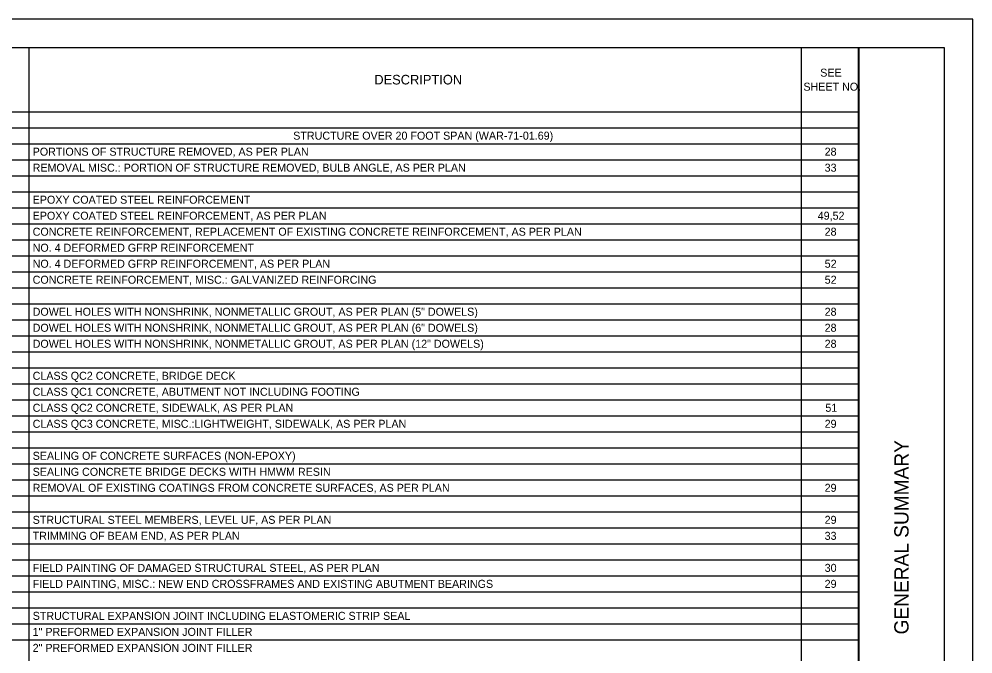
# Model space of a CAD drawing. Extents: x 0 to 34, y 0 to 22.
# Drawn here: x 17.32 to 34, y 10.89 to 22 of the extents above; entities that cross this region are included whole.
import ezdxf

# ---------------------------------------------------------------- set-up
doc = ezdxf.new("R2010")
doc.units = 0
for name, color, linetype in [('Default', 7, 'Continuous'), ('SH_Border', 7, 'Continuous'), ('SH_Cut_Line', 7, 'Continuous'), ('SH_Data', 7, 'Continuous')]:
    doc.layers.add(name, color=color, linetype=linetype)

msp = doc.modelspace()

# ---------------------------------------------------------------- linework, layer by layer
at = {"layer": 'Default'}
for p, q in [((1.5, 21.5), (32.004, 21.5)), ((17.493, 21.5), (17.493, 0.5)), ((30.999, 21.5), (30.999, 0.5)), ((32.004, 21.5), (32.004, 0.5)), ((1.5, 20.38), (32.004, 20.38)), ((1.5, 20.1), (32.004, 20.1)), ((1.5, 19.82), (32.004, 19.82)), ((1.5, 19.54), (32.004, 19.54)), ((1.5, 19.26), (32.004, 19.26)), ((1.5, 18.98), (32.004, 18.98)), ((1.5, 18.7), (32.004, 18.7)), ((1.5, 18.42), (32.004, 18.42)), ((1.5, 18.14), (32.004, 18.14)), ((1.5, 17.86), (32.004, 17.86)), ((1.5, 17.58), (32.004, 17.58)), ((1.5, 17.3), (32.004, 17.3)), ((1.5, 17.02), (32.004, 17.02)), ((1.5, 16.74), (32.004, 16.74)), ((1.5, 16.46), (32.004, 16.46)), ((1.5, 16.18), (32.004, 16.18)), ((1.5, 15.9), (32.004, 15.9)), ((1.5, 15.62), (32.004, 15.62)), ((1.5, 15.34), (32.004, 15.34)), ((1.5, 15.06), (32.004, 15.06)), ((1.5, 14.78), (32.004, 14.78)), ((1.5, 14.5), (32.004, 14.5)), ((1.5, 14.22), (32.004, 14.22)), ((1.5, 13.94), (32.004, 13.94)), ((1.5, 13.66), (32.004, 13.66)), ((1.5, 13.38), (32.004, 13.38)), ((1.5, 13.1), (32.004, 13.1)), ((1.5, 12.82), (32.004, 12.82)), ((1.5, 12.54), (32.004, 12.54)), ((1.5, 12.26), (32.004, 12.26)), ((1.5, 11.98), (32.004, 11.98)), ((1.5, 11.7), (32.004, 11.7)), ((1.5, 11.42), (32.004, 11.42)), ((1.5, 11.14), (32.004, 11.14))]:
    msp.add_line(p, q, dxfattribs=at)
at = {"layer": 'SH_Border'}
msp.add_line((32, 0.5), (32, 21.5), dxfattribs=at)
msp.add_lwpolyline([(1.5, 21.5), (33.5, 21.5), (33.5, 0.5), (1.5, 0.5)], close=True, dxfattribs=at)
at = {"layer": 'SH_Cut_Line'}
msp.add_lwpolyline([(0, 0), (34, 0), (34, 22), (0, 22)], close=True, dxfattribs=at)

# ---------------------------------------------------------------- texts
at = {"layer": 'Default'}
for s, height, p in [('DESCRIPTION', 0.168, (23.533, 20.856)), ('SEE ', 0.14, (31.33, 20.992)), ('SHEET NO.', 0.14, (31.036, 20.747)), ('STRUCTURE OVER 20 FOOT SPAN (WAR-71-01.69)', 0.14, (22.115, 19.89)), ('PORTIONS OF STRUCTURE REMOVED, AS PER PLAN', 0.14, (17.559, 19.61)), ('28', 0.14, (31.407, 19.61)), ('REMOVAL MISC.: PORTION OF STRUCTURE REMOVED, BULB ANGLE, AS PER PLAN', 0.14, (17.559, 19.33)), ('33', 0.14, (31.407, 19.33)), ('EPOXY COATED STEEL REINFORCEMENT', 0.14, (17.559, 18.77)), ('EPOXY COATED STEEL REINFORCEMENT, AS PER PLAN', 0.14, (17.559, 18.49)), ('49,52', 0.14, (31.286, 18.49)), ('CONCRETE REINFORCEMENT, REPLACEMENT OF EXISTING CONCRETE REINFORCEMENT, AS PER PLAN', 0.14, (17.559, 18.21)), ('28', 0.14, (31.407, 18.21)), ('NO. 4 DEFORMED GFRP REINFORCEMENT', 0.14, (17.559, 17.93)), ('NO. 4 DEFORMED GFRP REINFORCEMENT, AS PER PLAN', 0.14, (17.559, 17.65)), ('52', 0.14, (31.408, 17.65)), ('CONCRETE REINFORCEMENT, MISC.: GALVANIZED REINFORCING', 0.14, (17.559, 17.37)), ('52', 0.14, (31.408, 17.37)), ('DOWEL HOLES WITH NONSHRINK, NONMETALLIC GROUT, AS PER PLAN (5" DOWELS)', 0.14, (17.559, 16.81)), ('28', 0.14, (31.407, 16.81)), ('DOWEL HOLES WITH NONSHRINK, NONMETALLIC GROUT, AS PER PLAN (6" DOWELS)', 0.14, (17.559, 16.53)), ('28', 0.14, (31.407, 16.53)), ('DOWEL HOLES WITH NONSHRINK, NONMETALLIC GROUT, AS PER PLAN (12" DOWELS)', 0.14, (17.559, 16.25)), ('28', 0.14, (31.407, 16.25)), ('CLASS QC2 CONCRETE, BRIDGE DECK', 0.14, (17.559, 15.69)), ('CLASS QC1 CONCRETE, ABUTMENT NOT INCLUDING FOOTING', 0.14, (17.559, 15.41)), ('CLASS QC2 CONCRETE, SIDEWALK, AS PER PLAN', 0.14, (17.559, 15.13)), ('51', 0.14, (31.42, 15.13)), ('CLASS QC3 CONCRETE, MISC.:LIGHTWEIGHT, SIDEWALK, AS PER PLAN', 0.14, (17.559, 14.85)), ('29', 0.14, (31.407, 14.85)), ('SEALING OF CONCRETE SURFACES (NON-EPOXY)', 0.14, (17.559, 14.29)), ('SEALING CONCRETE BRIDGE DECKS WITH HMWM RESIN', 0.14, (17.559, 14.01)), ('REMOVAL OF EXISTING COATINGS FROM CONCRETE SURFACES, AS PER PLAN', 0.14, (17.559, 13.73)), ('29', 0.14, (31.407, 13.73)), ('STRUCTURAL STEEL MEMBERS, LEVEL UF, AS PER PLAN', 0.14, (17.559, 13.17)), ('29', 0.14, (31.407, 13.17)), ('TRIMMING OF BEAM END, AS PER PLAN', 0.14, (17.559, 12.89)), ('33', 0.14, (31.407, 12.89)), ('FIELD PAINTING OF DAMAGED STRUCTURAL STEEL, AS PER PLAN', 0.14, (17.559, 12.33)), ('30', 0.14, (31.408, 12.33)), ('FIELD PAINTING, MISC.: NEW END CROSSFRAMES AND EXISTING ABUTMENT BEARINGS', 0.14, (17.559, 12.05)), ('29', 0.14, (31.407, 12.05)), ('STRUCTURAL EXPANSION JOINT INCLUDING ELASTOMERIC STRIP SEAL', 0.14, (17.559, 11.49)), ('1" PREFORMED EXPANSION JOINT FILLER', 0.14, (17.559, 11.21)), ('2" PREFORMED EXPANSION JOINT FILLER', 0.14, (17.559, 10.93))]:
    msp.add_text(s, height=height, dxfattribs=at).set_placement(p)
at = {"layer": 'SH_Data'}
msp.add_text('GENERAL SUMMARY', height=0.25, rotation=90, dxfattribs=at).set_placement((32.875, 11.235))

doc.saveas('drawing.dxf')
